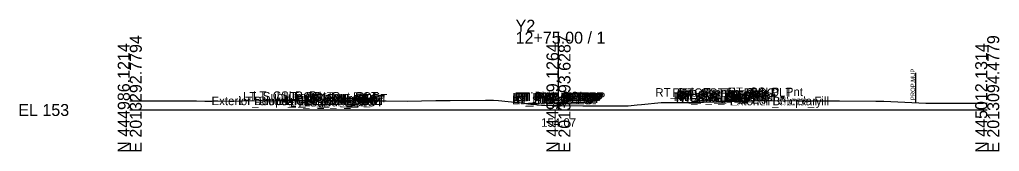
# Model space of a CAD drawing. Extents: x -26 to 203, y -10 to 6017.
# Drawn here: x -25.7 to 202.8, y 5490.3 to 5521.1 of the extents above; entities that cross this region are included whole.
import ezdxf

# ---------------------------------------------------------------- set-up
doc = ezdxf.new("R2010")
doc.units = 0
for name, color, linetype in [('Default', 7, 'Continuous'), ('Exist Cross Section Cell', 7, 'Continuous'), ('Exist XS Center Line Elevation Label', 7, 'Continuous'), ('Exist XS Ground Line', 7, 'Continuous'), ('Prop XS Label Text', 7, 'Continuous'), ('Scratch_Level_0', 7, 'Continuous')]:
    doc.layers.add(name, color=color, linetype=linetype)

msp = doc.modelspace()

# ---------------------------------------------------------------- linework, layer by layer
at = {"layer": 'Exist Cross Section Cell'}
for p, q in [((100, 5500), (100, 5518.31)), ((0, 5500), (100, 5500)), ((100, 5500), (200, 5500))]:
    msp.add_line(p, q, dxfattribs=at)
at = {"layer": 'Exist XS Ground Line'}
msp.add_lwpolyline([(0, 5502.13), (15.54, 5502.11), (17.53, 5502.07), (19.11, 5502.1), (26.3, 5502.16), (34.41, 5502.24), (41.68, 5502.2), (44.5, 5502.18), (48.16, 5502.15), (54.59, 5502.15), (59.77, 5502.13), (64.67, 5502.09), (71.38, 5502.19), (74.76, 5502.19), (82.99, 5502.27), (84.85, 5502.29), (86, 5502.19), (94.29, 5501.35), (95.04, 5501.23), (96.05, 5501.12), (100, 5501.07), (105.65, 5501.01), (106.86, 5500.98), (115.33, 5500.94), (116.27, 5500.94), (118.34, 5501.19), (119.36, 5501.29), (123.92, 5501.74), (128.21, 5501.74), (130.68, 5501.74), (139.99, 5502), (145.37, 5502.17), (152.65, 5502.19), (155.45, 5502.16), (164.26, 5502.13), (165.54, 5502.12), (174.02, 5502.06), (175.87, 5502.04), (185.71, 5501.62), (187.48, 5501.57), (195.8, 5501.57), (199.09, 5501.63), (200, 5501.64)], dxfattribs=at)
at = {"layer": 'Prop XS Label Text'}
msp.add_line((183.25, 5508.72), (183.25, 5501.72), dxfattribs=at)

# ---------------------------------------------------------------- texts
at = {"layer": 'Default'}
msp.add_text('-', height=0.0001, dxfattribs=at).set_placement((0, 5500))
at = {"layer": 'Exist Cross Section Cell'}
for s, p in [('Y2', (90, 5518.31)), ('12+75.00 / 1', (90, 5515.51)), ('EL 153', (-26, 5498.6))]:
    msp.add_text(s, height=2.8, dxfattribs=at).set_placement(p)
for s, p in [('E 2013292.7794', (2.8, 5490)), ('E 2013193.6287', (102.8, 5490)), ('E 2013094.4779', (202.8, 5490)), ('N 444986.1214', (0, 5490)), ('N 444999.1264', (100, 5490)), ('N 445012.1314', (200, 5490))]:
    msp.add_text(s, height=2.8, rotation=90, dxfattribs=at).set_placement(p)
at = {"layer": 'Exist XS Center Line Elevation Label'}
msp.add_text('154.07', height=2, dxfattribs=at).set_placement((95.94, 5496.07))
at = {"layer": 'Prop XS Label Text'}
msp.add_text('PROP.MUP', height=1, rotation=90, dxfattribs=at).set_placement((183.15, 5502.3))
at = {"layer": 'Scratch_Level_0'}
for s, p in [('Exterior Boundary', (19.07, 5501.13)), ('LT_Slope_Fill', (25.44, 5501.13)), ('LT_Sub_Trench_Out_DLT', (26.42, 5502.21)), ('LT_CSLP_Pnt', (28.76, 5502.35)), ('LT_CG1_Shelf_Out', (34.14, 5501.15)), ('LT_CG_Top_Face', (35.85, 5502.16)), ('LT_CG_Top_BOC', (36.37, 5502.16)), ('LT_CG_Bot_BOC', (36.41, 5501.15)), ('LT_CG_Top_Gut', (36.83, 5501.66)), ('LT_CG_Bot_IE', (40.51, 5501.18)), ('LT_PV2_OEOT', (40.77, 5501.51)), ('LT_PV3_OEOT', (40.77, 5501.18)), ('LT_PV1_OEOT', (41.33, 5501.76)), ('RT_Sub_OEEOP', (89.15, 5501.34)), ('LT_Sub_OEEOP', (89.19, 5501.34)), ('RT_PV2_OEEOP', (89.24, 5502)), ('RT_PV3_OEEOP', (89.24, 5501.67)), ('LT_PV2_OEEOP', (89.29, 5502)), ('LT_PV3_OEEOP', (89.29, 5501.67)), ('RT_PV1_OEEOP', (89.81, 5502.13)), ('LT_PV1_OEEOP', (89.85, 5502.13)), ('RT_PV2_IEEOP', (89.89, 5502)), ('LT_PV2_IEEOP', (89.93, 5502)), ('RT_PV1_IEEOP', (90.45, 5502.13)), ('LT_PV1_IEEOP', (90.5, 5502.13)), ('PV2_PGL', (93.89, 5502)), ('PV1_PGL', (94.45, 5502.25)), ('RT_Sub_Trench_Out_DLT', (122.58, 5503.11)), ('RT_CG_Top_Face', (126.58, 5503.06)), ('RT_CG1_Shelf_Out', (126.87, 5502.07)), ('RT_CG_Bot_IE', (127.23, 5502.04)), ('RT_Sub_OEOT', (127.4, 5501.71)), ('RT_PV2_OEOT', (127.49, 5502.37)), ('RT_PV3_OEOT', (127.49, 5502.04)), ('RT_CG_Top_Gut', (127.56, 5502.56)), ('RT_PV1_OEOT', (128.06, 5502.62)), ('RT_CG_Top_BOC', (128.1, 5503.06)), ('RT_CG_Bot_BOC', (128.13, 5502.07)), ('RT_Sub_OEOP', (130.76, 5501.74)), ('RT_CSLP_Pnt', (139.49, 5503.25)), ('Exterior Boundary', (139.97, 5501.1)), ('RT_Slope_Fill', (146.3, 5501.1)), ('LT_Sub_OEOP', (37.36, 5500.81)), ('LT_Sub_OEOT', (40.67, 5500.84))]:
    msp.add_text(s, height=2, dxfattribs=at).set_placement(p)

doc.saveas('drawing.dxf')
